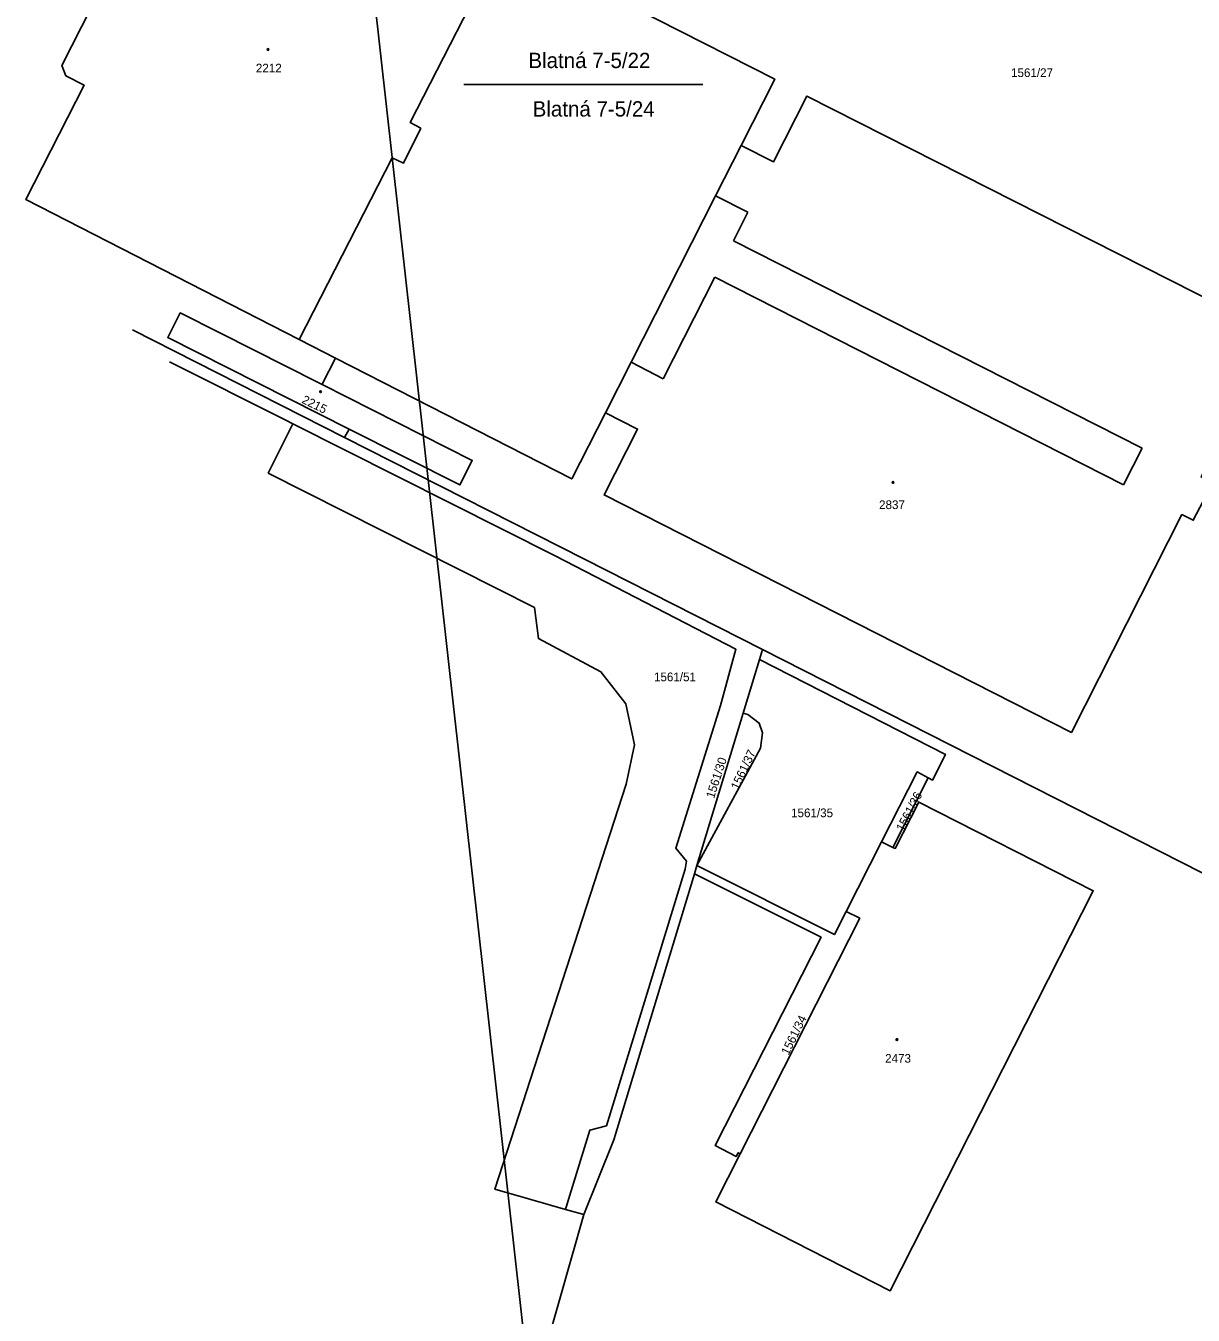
# Model space of a CAD drawing. Extents: x -793666 to -785424, y -1118958 to -1108761.
# Drawn here: x -792861.7 to -792633.4, y -1110740.7 to -1110488.5 of the extents above; entities that cross this region are included whole.
import ezdxf

# ---------------------------------------------------------------- set-up
doc = ezdxf.new("R2010")
doc.units = 0
for name, color, linetype in [('1', 7, 'Continuous'), ('1_2000 - úřady', 7, 'Continuous'), ('Hranice parcel', 7, 'Continuous'), ('Parcelní čísla', 7, 'Continuous'), ('Vnitřní kresba', 7, 'Continuous'), ('Značky budov', 7, 'Continuous')]:
    doc.layers.add(name, color=color, linetype=linetype)

msp = doc.modelspace()

# ---------------------------------------------------------------- linework, layer by layer
at = {"layer": '1'}
msp.add_line((-792729.32, -1110500), (-792776.04, -1110500), dxfattribs=at)
at = {"layer": '1_2000 - úřady'}
msp.add_lwpolyline([(-792522.06, -1110204.41), (-792422.02, -1111099.6), (-792720.93, -1111133), (-792820.96, -1110237.81)], close=True, dxfattribs=at)
at = {"layer": 'Hranice parcel'}
for p, q in [((-792840.87, -1110547.97), (-792799.39, -1110569.04)), ((-792814.36, -1110576.02), (-792809.5, -1110566.39)), ((-792799.39, -1110569.04), (-792798.52, -1110567.4)), ((-792717.66, -1110610.53), (-792718.24, -1110612.44)), ((-792717.66, -1110610.53), (-792591.1, -1110674.8)), ((-792721.42, -1110622.95), (-792718.24, -1110612.44)), ((-792730.46, -1110652.76), (-792721.42, -1110622.95)), ((-792685.22, -1110635.61), (-792692.14, -1110649.21)), ((-792701.25, -1110661.74), (-792694.38, -1110648.11)), ((-792694.38, -1110648.11), (-792692.14, -1110649.21)), ((-792730.96, -1110654.38), (-792730.46, -1110652.76)), ((-792752.56, -1110721.04), (-792776.5, -1110804.34)), ((-792756.17, -1110720.02), (-792752.56, -1110721.04))]:
    msp.add_line(p, q, dxfattribs=at)
for points in [[(-792761.23, -1110475.55), (-792768.36, -1110471.92), (-792821.87, -1110444.63), (-792833.35, -1110467.07), (-792836.92, -1110465.24), (-792839.29, -1110466.05), (-792845.03, -1110477.35), (-792844.59, -1110477.44), (-792848.33, -1110485.09), (-792848.86, -1110484.89), (-792854.67, -1110496.33), (-792853.9, -1110498.34), (-792850.3, -1110500.18), (-792861.74, -1110522.54), (-792808.28, -1110549.91), (-792801.15, -1110553.55)], [(-792721.79, -1110511.93), (-792715.21, -1110499), (-792761.23, -1110475.55)], [(-792721.79, -1110511.93), (-792715.49, -1110515.15), (-792708.94, -1110502.27), (-792617.55, -1110548.61), (-792617.98, -1110549.46), (-792615.07, -1110550.92), (-792617.03, -1110554.92), (-792619.99, -1110553.41), (-792631.85, -1110576.75), (-792629.58, -1110577.89), (-792633.4, -1110585.25), (-792635.6, -1110584.14), (-792657.23, -1110626.73), (-792748.62, -1110580.29), (-792742.08, -1110567.4), (-792748.36, -1110564.21)], [(-792748.36, -1110564.21), (-792743.32, -1110554.29), (-792726.81, -1110521.82), (-792721.79, -1110511.93)], [(-792803.79, -1110558.7), (-792804.71, -1110558.23), (-792810.76, -1110555.18), (-792823.8, -1110548.59), (-792831.53, -1110544.69), (-792833.96, -1110549.51), (-792798.52, -1110567.4)], [(-792833.61, -1110554.24), (-792810.9, -1110565.68), (-792809.5, -1110566.39)], [(-792803.79, -1110558.7), (-792803.68, -1110558.49), (-792801.15, -1110553.55)], [(-792801.15, -1110553.55), (-792754.94, -1110577.15), (-792748.36, -1110564.21)], [(-792798.52, -1110567.4), (-792776.83, -1110578.34), (-792774.4, -1110573.53), (-792803.79, -1110558.7)], [(-792809.5, -1110566.39), (-792758.18, -1110592.2), (-792722.84, -1110610.45), (-792725.84, -1110621.49), (-792734.61, -1110649.36), (-792732.48, -1110651.94), (-792732.74, -1110653.49), (-792748.18, -1110703.64), (-792751.42, -1110704.51), (-792755.84, -1110718.93), (-792756.17, -1110720.02)], [(-792799.39, -1110569.04), (-792752.45, -1110592.87), (-792717.66, -1110610.53)], [(-792756.17, -1110720.02), (-792762.96, -1110718.07), (-792769.97, -1110716.07), (-792744.33, -1110636.87), (-792742.66, -1110629.19), (-792744.4, -1110621.12), (-792749.24, -1110614.88), (-792761.47, -1110608.37), (-792762.23, -1110602.33), (-792814.36, -1110576.02)], [(-792718.24, -1110612.44), (-792681.86, -1110631.03), (-792684.41, -1110636.07), (-792685.22, -1110635.61)], [(-792721.42, -1110622.95), (-792720.53, -1110623.24), (-792718.31, -1110624.92), (-792717.67, -1110626.82), (-792718.01, -1110629.81), (-792730.46, -1110652.76)], [(-792694.38, -1110648.11), (-792687.38, -1110634.45), (-792685.22, -1110635.61)], [(-792692.14, -1110649.21), (-792691.69, -1110649.43), (-792687.06, -1110640.34), (-792652.95, -1110657.7), (-792692.66, -1110735.91), (-792726.8, -1110718.56), (-792722.01, -1110709.13)], [(-792701.25, -1110661.74), (-792703.57, -1110666.28), (-792730.46, -1110652.76)], [(-792730.96, -1110654.38), (-792746.73, -1110706.41), (-792752.56, -1110721.04)], [(-792722.01, -1110709.13), (-792722.4, -1110708.94), (-792722.8, -1110709.69), (-792726.88, -1110707.53), (-792706.14, -1110666.79), (-792730.96, -1110654.38)], [(-792722.01, -1110709.13), (-792698.61, -1110663.07), (-792701.25, -1110661.74)]]:
    msp.add_lwpolyline(points, dxfattribs=at)
at = {"layer": 'Vnitřní kresba'}
for p, q in [((-792726.81, -1110521.82), (-792720.49, -1110525.01)), ((-792720.49, -1110525.01), (-792723.33, -1110530.62)), ((-792723.33, -1110530.62), (-792643.41, -1110571.15)), ((-792737.04, -1110557.56), (-792726.95, -1110537.73)), ((-792726.95, -1110537.73), (-792647.05, -1110578.32)), ((-792743.32, -1110554.29), (-792737.04, -1110557.56)), ((-792643.41, -1110571.15), (-792647.05, -1110578.32))]:
    msp.add_line(p, q, dxfattribs=at)
for points in [[(-792784.44, -1110508.55), (-792786.55, -1110507.47), (-792768.36, -1110471.92)], [(-792808.28, -1110549.91), (-792790.07, -1110514.34), (-792787.84, -1110515.38), (-792784.44, -1110508.55)]]:
    msp.add_lwpolyline(points, dxfattribs=at)
at = {"layer": 'Značky budov'}
for centre in [(-792814.37, -1110493.17), (-792804.07, -1110560.09), (-792692.12, -1110577.83), (-792691.35, -1110686.8)]:
    msp.add_circle(centre, 0.175, dxfattribs=at)

# ---------------------------------------------------------------- texts
at = {"layer": '1'}
for s, p in [('Blatná 7-5/22', (-792763.43, -1110496.81)), ('Blatná 7-5/24', (-792762.6, -1110506.29))]:
    msp.add_text(s, height=3, dxfattribs=at).set_placement(p)
at = {"layer": 'Parcelní čísla'}
for s, p in [('2212', (-792816.74, -1110497.66)), ('1561/27', (-792669.03, -1110498.56)), ('2837', (-792694.84, -1110583.05)), ('1561/51', (-792738.87, -1110616.72)), ('1561/35', (-792712.05, -1110643.31)), ('2473', (-792693.66, -1110691.32))]:
    msp.add_text(s, height=1.7, dxfattribs=at).set_placement(p)
for s, rotation, p in [('2215', 334, (-792807.9, -1110562.23)), ('1561/37', 65, (-792722.38, -1110638.09)), ('1561/30', 72, (-792727.13, -1110639.77)), ('1561/36', 63, (-792690.07, -1110646.23)), ('1561/34', 64, (-792712.55, -1110689.97))]:
    msp.add_text(s, height=1.7, rotation=rotation, dxfattribs=at).set_placement(p)

doc.saveas('drawing.dxf')
